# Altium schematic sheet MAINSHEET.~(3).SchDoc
size 594 x 420 mm; Scale: 1:1; Разраб.: Иванов; Обозначение документа: АБВГ.123456.001 Э3; Пров.: Петров; Утв.: Сидоров; Наименование организации: ОАО "Концерн "МПО-Гидроприбор"; Перв. применение: АБВГ.123456.000; Наименование изделия 1: Плата; Наименование изделия 2: Схема электрическая; Наименование изделия 3: принципиальная; Нач. отд.: Нач. отд.; Фамилия нач. отд.: Сидоров
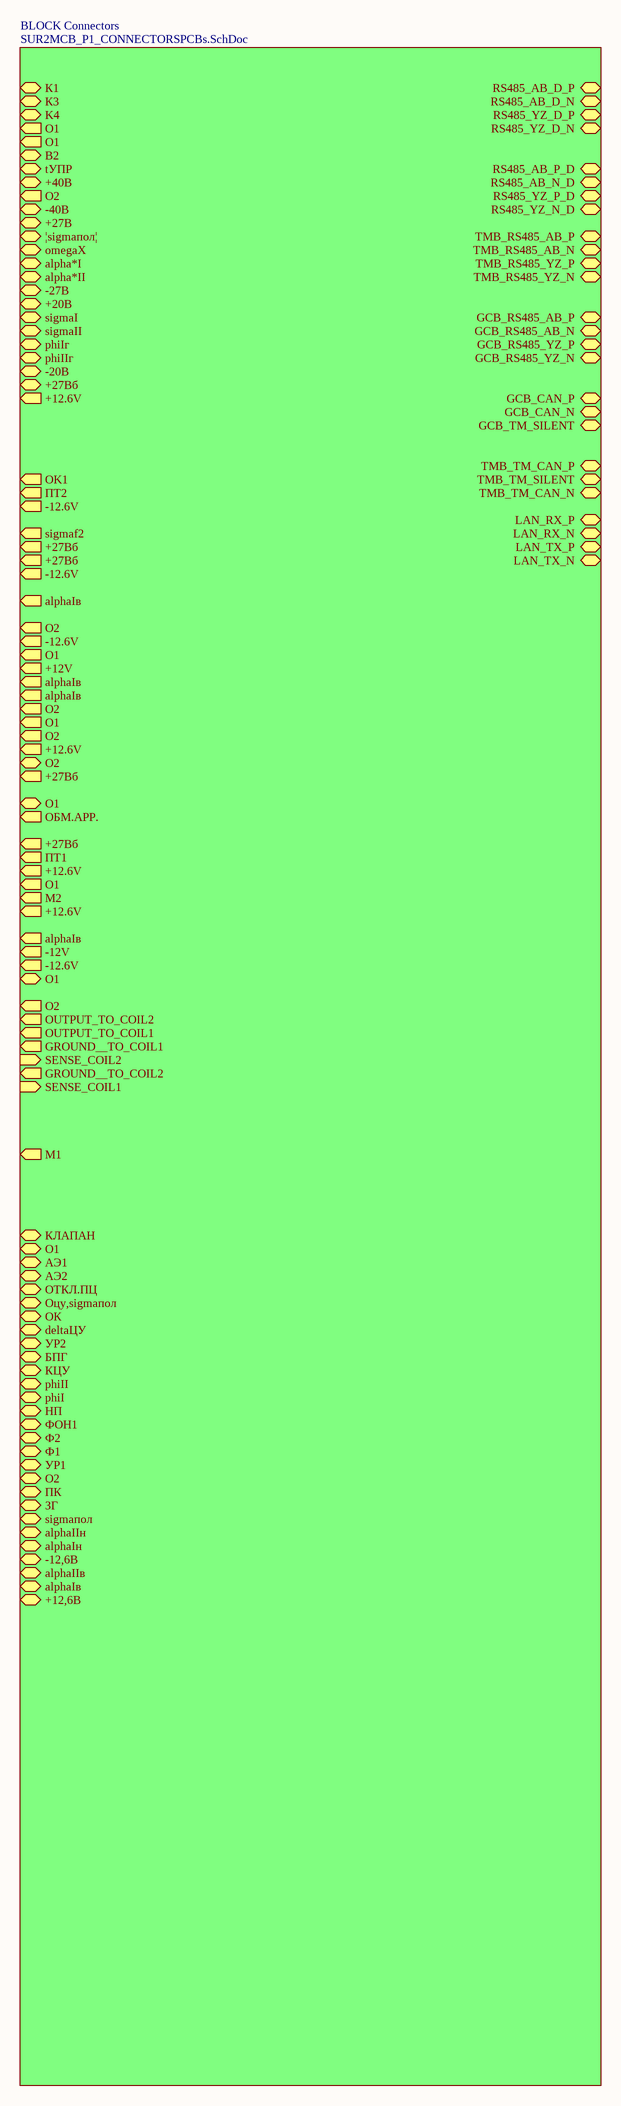
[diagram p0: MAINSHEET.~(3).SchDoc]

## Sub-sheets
BLOCK Connectors = SUR2MCB_P1_CONNECTORSPCBs.SchDoc: OK1 (out), ПТ2 (out), O1 (out), -12.6V (out), O2 (out), sigmaf2 (out), +27Вб (out), +27Вб (out), -12.6V (out), tУПР (bidir), B2 (bidir), O1 (out), alphaIв (out), O2 (out), -12.6V (out), O1 (out), +12V (out), alphaIв (out), alphaIв (out), O2 (out), O1 (out), O2 (out), +12.6V (out), О2 (bidir), +27Вб (out), K4 (bidir), O1 (bidir), ОБМ.АРР. (out), +40В (bidir), +27Вб (out), ПТ1 (out), +12.6V (out), O1 (out), M2 (out), +12.6V (out), К1 (bidir), alphaIв (out), -12V (out), -12.6V (out), O1 (bidir), К3 (bidir), O2 (out), OUTPUT_TO_COIL2 (out), OUTPUT_TO_COIL1 (out), GROUND__TO_COIL1 (out), SENSE_COIL2 (in), GROUND__TO_COIL2 (out), SENSE_COIL1 (in), RS485_YZ_D_N (bidir), RS485_YZ_D_P (bidir), RS485_AB_D_N (bidir), M1 (out), RS485_AB_D_P (bidir), RS485_YZ_N_D (bidir), КЛАПАН (bidir), О1 (bidir), АЭ1 (bidir), АЭ2 (bidir), ОТКЛ.ПЦ (bidir), Оцу,sigmaпол (bidir), ОК (bidir), deltaЦУ (bidir), УР2 (bidir), БПГ (bidir), КЦУ (bidir), phiII (bidir), phiI (bidir), НП (bidir), ФОН1 (bidir), Ф2 (bidir), Ф1 (bidir), УР1 (bidir), O2 (bidir), ПК (bidir), ЗГ (bidir), sigmaпол (bidir), alphaIIн (bidir), alphaIн (bidir), -12,6В (bidir), alphaIIв (bidir), alphaIв (bidir), +12,6В (bidir), RS485_AB_P_D (bidir), RS485_AB_N_D (bidir), RS485_YZ_P_D (bidir), TMB_RS485_AB_N (bidir), TMB_RS485_AB_P (bidir), TMB_RS485_YZ_N (bidir), TMB_RS485_YZ_P (bidir), LAN_RX_P (bidir), LAN_RX_N (bidir), LAN_TX_P (bidir), LAN_TX_N (bidir), GCB_RS485_AB_N (bidir), GCB_RS485_YZ_N (bidir), GCB_RS485_YZ_P (bidir), GCB_RS485_AB_P (bidir), GCB_CAN_P (bidir), GCB_CAN_N (bidir), GCB_TM_SILENT (bidir), TMB_TM_CAN_P (bidir), TMB_TM_SILENT (bidir), TMB_TM_CAN_N (bidir), -40В (bidir), +27В (bidir), ¦sigmaпол¦ (bidir), omegaX (bidir), alpha*II (bidir), alpha*I (bidir), -27В (bidir), +20В (bidir), -20В (bidir), sigmaII (bidir), sigmaI (bidir), phiIIг (bidir), phiIг (bidir), +27Вб (bidir), +12.6V (out)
